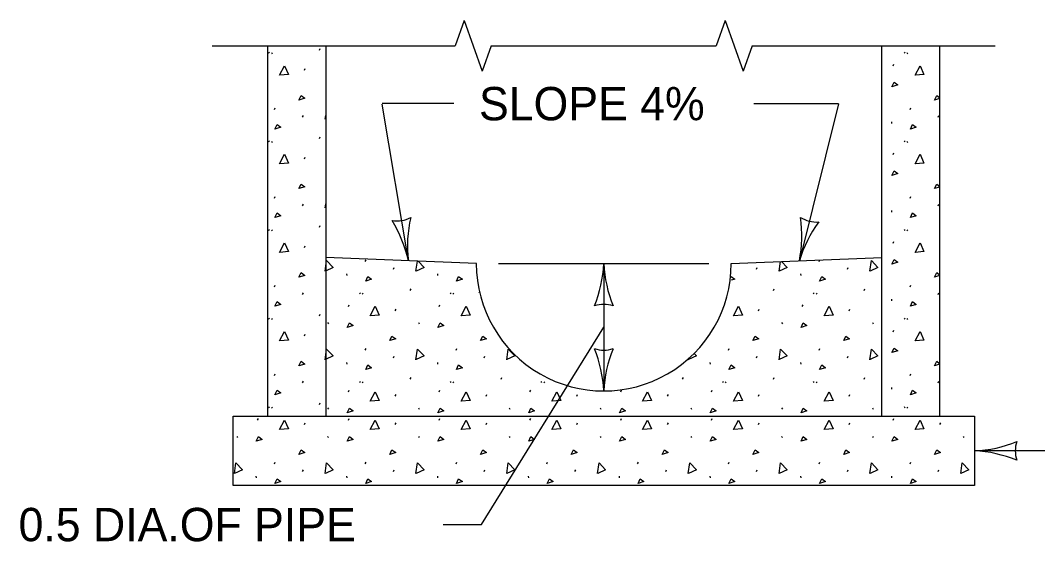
# Model space of a CAD drawing. Extents: x 49991.4 to 50028.3, y 49987.6 to 50011.4.
# Drawn here: x 50003.378 to 50005.208, y 49995.084 to 49996.022 of the extents above; entities that cross this region are included whole.
import ezdxf

# ---------------------------------------------------------------- set-up
doc = ezdxf.new("R2010")
doc.units = 0
for name, color, linetype in [('Level 1', 7, 'Continuous'), ('Level 2', 7, 'Continuous'), ('Level 3', 7, 'Continuous'), ('Level 6', 7, 'Continuous')]:
    doc.layers.add(name, color=color, linetype=linetype)

msp = doc.modelspace()

# ---------------------------------------------------------------- linework, layer by layer
at = {"layer": 'Level 1'}
for p, q in [((50003.8231, 49995.3096), (50003.8231, 49995.9763)), ((50003.9272, 49995.9763), (50003.9272, 49995.3096)), ((50004.9272, 49995.3096), (50004.9272, 49995.9763)), ((50005.0313, 49995.9763), (50005.0313, 49995.3096)), ((50003.8244, 49995.9647), (50003.8257, 49995.9627)), ((50003.8295, 49995.9639), (50003.8308, 49995.9619)), ((50003.9161, 49995.9686), (50003.9174, 49995.9716)), ((50004.9673, 49995.9647), (50004.9686, 49995.9627)), ((50004.9723, 49995.9639), (50004.9737, 49995.9619)), ((50004.9476, 49995.94), (50004.9489, 49995.943)), ((50003.8891, 49995.9323), (50003.8904, 49995.9353)), ((50003.8351, 49995.8614), (50003.8365, 49995.8644)), ((50003.8857, 49995.8478), (50003.8871, 49995.8508)), ((50004.978, 49995.8614), (50004.9793, 49995.8644)), ((50005.0286, 49995.8478), (50005.0299, 49995.8508)), ((50004.9445, 49995.8394), (50004.9449, 49995.8364)), ((50003.9161, 49995.8091), (50003.9174, 49995.8121)), ((50003.8244, 49995.8052), (50003.8257, 49995.8032)), ((50003.8295, 49995.8044), (50003.8308, 49995.8024)), ((50004.9673, 49995.8052), (50004.9686, 49995.8032)), ((50004.9723, 49995.8044), (50004.9737, 49995.8024)), ((50003.8891, 49995.7729), (50003.8904, 49995.7759)), ((50004.9476, 49995.7805), (50004.9489, 49995.7835)), ((50003.8351, 49995.702), (50003.8365, 49995.705)), ((50004.978, 49995.702), (50004.9793, 49995.705)), ((50003.8857, 49995.6883), (50003.8871, 49995.6913)), ((50005.0286, 49995.6883), (50005.0299, 49995.6913)), ((50004.9445, 49995.6799), (50004.9449, 49995.6769)), ((50003.8244, 49995.6458), (50003.8257, 49995.6438)), ((50003.9161, 49995.6497), (50003.9174, 49995.6526)), ((50004.9673, 49995.6458), (50004.9686, 49995.6438)), ((50003.8295, 49995.645), (50003.8308, 49995.643)), ((50004.9723, 49995.645), (50004.9737, 49995.643)), ((50003.8891, 49995.6134), (50003.8904, 49995.6164)), ((50004.9476, 49995.6211), (50004.9489, 49995.6241)), ((50004.1981, 49995.5842), (50003.9272, 49995.5955)), ((50003.9984, 49995.5879), (50003.9997, 49995.5909)), ((50004.6564, 49995.5842), (50004.9272, 49995.5955)), ((50004.8147, 49995.5879), (50004.8161, 49995.5908)), ((50004.049, 49995.5742), (50004.0503, 49995.5772)), ((50004.7021, 49995.5742), (50004.7034, 49995.5772)), ((50004.8653, 49995.5742), (50004.8667, 49995.5772)), ((50003.9649, 49995.5659), (50003.9653, 49995.5629)), ((50004.1282, 49995.5659), (50004.1285, 49995.5629)), ((50004.7813, 49995.5659), (50004.7816, 49995.5629)), ((50003.8351, 49995.5425), (50003.8365, 49995.5455)), ((50004.0793, 49995.5356), (50004.0807, 49995.5386)), ((50004.7324, 49995.5356), (50004.7337, 49995.5386)), ((50004.8957, 49995.5356), (50004.897, 49995.5386)), ((50004.978, 49995.5425), (50004.9793, 49995.5455)), ((50003.8857, 49995.5288), (50003.8871, 49995.5318)), ((50003.9877, 49995.5317), (50003.989, 49995.5297)), ((50003.9927, 49995.531), (50003.9941, 49995.529)), ((50004.1509, 49995.5317), (50004.1523, 49995.5297)), ((50004.156, 49995.531), (50004.1573, 49995.529)), ((50004.804, 49995.5317), (50004.8053, 49995.5297)), ((50004.8091, 49995.531), (50004.8104, 49995.529)), ((50004.9445, 49995.5205), (50004.9449, 49995.5175)), ((50005.0286, 49995.5288), (50005.0299, 49995.5318)), ((50003.968, 49995.507), (50003.9693, 49995.51)), ((50004.0523, 49995.4994), (50004.0537, 49995.5024)), ((50004.1313, 49995.507), (50004.1326, 49995.51)), ((50004.7054, 49995.4994), (50004.7067, 49995.5024)), ((50004.7843, 49995.507), (50004.7857, 49995.51)), ((50004.8687, 49995.4994), (50004.87, 49995.5024)), ((50003.8244, 49995.4863), (50003.8257, 49995.4843)), ((50003.8295, 49995.4856), (50003.8308, 49995.4836)), ((50003.9161, 49995.4902), (50003.9174, 49995.4932)), ((50004.9673, 49995.4863), (50004.9686, 49995.4843)), ((50004.9723, 49995.4856), (50004.9737, 49995.4836)), ((50003.9307, 49995.478), (50003.9321, 49995.476)), ((50004.094, 49995.478), (50004.0953, 49995.476)), ((50004.7471, 49995.478), (50004.7484, 49995.476)), ((50004.9103, 49995.478), (50004.9117, 49995.476)), ((50004.9476, 49995.4616), (50004.9489, 49995.4646)), ((50003.8891, 49995.454), (50003.8904, 49995.457)), ((50003.9984, 49995.4284), (50003.9997, 49995.4314)), ((50004.1617, 49995.4284), (50004.163, 49995.4314)), ((50004.6515, 49995.4284), (50004.6528, 49995.4314)), ((50004.8147, 49995.4284), (50004.8161, 49995.4314)), ((50004.049, 49995.4148), (50004.0503, 49995.4178)), ((50004.2123, 49995.4148), (50004.2136, 49995.4178)), ((50004.7021, 49995.4148), (50004.7034, 49995.4178)), ((50004.8653, 49995.4148), (50004.8667, 49995.4178)), ((50003.9649, 49995.4064), (50003.9653, 49995.4034)), ((50004.1282, 49995.4064), (50004.1285, 49995.4034)), ((50004.618, 49995.4064), (50004.6183, 49995.4034)), ((50004.7813, 49995.4064), (50004.7816, 49995.4034)), ((50003.8351, 49995.383), (50003.8365, 49995.386)), ((50003.8857, 49995.3694), (50003.8871, 49995.3724)), ((50003.9877, 49995.3722), (50003.989, 49995.3702)), ((50003.9927, 49995.3715), (50003.9941, 49995.3695)), ((50004.0793, 49995.3762), (50004.0807, 49995.3792)), ((50004.1509, 49995.3722), (50004.1523, 49995.3702)), ((50004.156, 49995.3715), (50004.1573, 49995.3695)), ((50004.2426, 49995.3762), (50004.2439, 49995.3792)), ((50004.3142, 49995.3722), (50004.3155, 49995.3702)), ((50004.3193, 49995.3715), (50004.3206, 49995.3695)), ((50004.5691, 49995.3762), (50004.5705, 49995.3792)), ((50004.6407, 49995.3722), (50004.6421, 49995.3702)), ((50004.6458, 49995.3715), (50004.6471, 49995.3695)), ((50004.7324, 49995.3762), (50004.7337, 49995.3792)), ((50004.804, 49995.3722), (50004.8053, 49995.3702)), ((50004.8091, 49995.3715), (50004.8104, 49995.3695)), ((50004.8957, 49995.3762), (50004.897, 49995.3792)), ((50004.978, 49995.383), (50004.9793, 49995.386)), ((50005.0286, 49995.3694), (50005.0299, 49995.3724)), ((50003.968, 49995.3534), (50003.9693, 49995.3564)), ((50004.1313, 49995.3534), (50004.1326, 49995.3564)), ((50004.2945, 49995.3534), (50004.2959, 49995.3564)), ((50004.4578, 49995.3534), (50004.4591, 49995.3564)), ((50004.6211, 49995.3534), (50004.6224, 49995.3564)), ((50004.9445, 49995.361), (50004.9449, 49995.358)), ((50004.0523, 49995.3457), (50004.0537, 49995.3487)), ((50004.2156, 49995.3457), (50004.2169, 49995.3487)), ((50004.3789, 49995.3457), (50004.3802, 49995.3487)), ((50004.5421, 49995.3457), (50004.5435, 49995.3487)), ((50004.7054, 49995.3457), (50004.7067, 49995.3487)), ((50004.8687, 49995.3457), (50004.87, 49995.3487)), ((50003.8244, 49995.3268), (50003.8257, 49995.3248)), ((50003.8295, 49995.3261), (50003.8308, 49995.3241)), ((50003.9161, 49995.3308), (50003.9174, 49995.3338)), ((50003.9307, 49995.3244), (50003.9321, 49995.3224)), ((50004.094, 49995.3244), (50004.0953, 49995.3224)), ((50004.2573, 49995.3244), (50004.2586, 49995.3224)), ((50004.4205, 49995.3244), (50004.4219, 49995.3224)), ((50004.5838, 49995.3244), (50004.5851, 49995.3224)), ((50004.7471, 49995.3244), (50004.7484, 49995.3224)), ((50004.9103, 49995.3244), (50004.9117, 49995.3224)), ((50004.9673, 49995.3268), (50004.9686, 49995.3248)), ((50004.9723, 49995.3261), (50004.9737, 49995.3241)), ((50003.7605, 49995.3096), (50005.0938, 49995.3096)), ((50003.7605, 49995.3096), (50005.0938, 49995.3096)), ((50003.7605, 49995.3096), (50005.0938, 49995.3096)), ((50003.7605, 49995.1846), (50003.7605, 49995.3096)), ((50003.8047, 49995.3022), (50003.8061, 49995.3052)), ((50003.8891, 49995.2945), (50003.8904, 49995.2975)), ((50003.968, 49995.3022), (50003.9693, 49995.3052)), ((50004.0523, 49995.2945), (50004.0537, 49995.2975)), ((50004.1313, 49995.3022), (50004.1326, 49995.3052)), ((50004.2156, 49995.2945), (50004.2169, 49995.2975)), ((50004.2945, 49995.3022), (50004.2959, 49995.3052)), ((50004.3789, 49995.2945), (50004.3802, 49995.2975)), ((50004.4578, 49995.3022), (50004.4591, 49995.3052)), ((50004.5421, 49995.2945), (50004.5435, 49995.2975)), ((50004.6211, 49995.3022), (50004.6224, 49995.3052)), ((50004.7054, 49995.2945), (50004.7067, 49995.2975)), ((50004.8687, 49995.2945), (50004.87, 49995.2975)), ((50004.9476, 49995.3022), (50004.9489, 49995.3052)), ((50005.0319, 49995.2945), (50005.0333, 49995.2975)), ((50005.0938, 49995.3096), (50005.0938, 49995.1846)), ((50003.7675, 49995.2732), (50003.7688, 49995.2712)), ((50003.9307, 49995.2732), (50003.9321, 49995.2712)), ((50004.094, 49995.2732), (50004.0953, 49995.2712)), ((50004.2573, 49995.2732), (50004.2586, 49995.2712)), ((50004.4205, 49995.2732), (50004.4219, 49995.2712)), ((50004.5838, 49995.2732), (50004.5851, 49995.2712)), ((50004.7471, 49995.2732), (50004.7484, 49995.2712)), ((50004.9103, 49995.2732), (50004.9117, 49995.2712)), ((50005.0736, 49995.2732), (50005.0749, 49995.2712)), ((50003.8351, 49995.2236), (50003.8365, 49995.2266)), ((50003.9984, 49995.2236), (50003.9997, 49995.2266)), ((50004.1617, 49995.2236), (50004.163, 49995.2266)), ((50004.3249, 49995.2236), (50004.3263, 49995.2266)), ((50004.4882, 49995.2236), (50004.4895, 49995.2266)), ((50004.6515, 49995.2236), (50004.6528, 49995.2266)), ((50004.8147, 49995.2236), (50004.8161, 49995.2266)), ((50004.978, 49995.2236), (50004.9793, 49995.2266)), ((50003.8857, 49995.2099), (50003.8871, 49995.2129)), ((50004.049, 49995.2099), (50004.0503, 49995.2129)), ((50004.2123, 49995.2099), (50004.2136, 49995.2129)), ((50004.3755, 49995.2099), (50004.3769, 49995.2129)), ((50004.5388, 49995.2099), (50004.5401, 49995.2129)), ((50004.7021, 49995.2099), (50004.7034, 49995.2129)), ((50004.8653, 49995.2099), (50004.8667, 49995.2129)), ((50005.0286, 49995.2099), (50005.0299, 49995.2129)), ((50003.8017, 49995.2016), (50003.802, 49995.1986)), ((50003.9649, 49995.2016), (50003.9653, 49995.1986)), ((50004.1282, 49995.2016), (50004.1285, 49995.1986)), ((50004.2915, 49995.2016), (50004.2918, 49995.1986)), ((50004.4547, 49995.2016), (50004.4551, 49995.1986)), ((50004.618, 49995.2016), (50004.6183, 49995.1986)), ((50004.7813, 49995.2016), (50004.7816, 49995.1986)), ((50004.9445, 49995.2016), (50004.9449, 49995.1986)), ((50005.0938, 49995.1846), (50003.7605, 49995.1846))]:
    msp.add_line(p, q, dxfattribs=at)
for points in [[(50003.8441, 49995.9234), (50003.8531, 49995.9403), (50003.8601, 49995.9247), (50003.8445, 49995.9234)], [(50004.987, 49995.9234), (50004.996, 49995.9403), (50005.003, 49995.9247), (50004.9873, 49995.9234)], [(50004.9453, 49995.9024), (50004.9493, 49995.9107), (50004.9559, 49995.9057), (50004.9453, 49995.9024)], [(50003.8791, 49995.8786), (50003.8831, 49995.8869), (50003.8898, 49995.8819), (50003.8791, 49995.8786)], [(50005.022, 49995.8786), (50005.026, 49995.8869), (50005.0313, 49995.8829)], [(50005.0313, 49995.8814), (50005.022, 49995.8786)], [(50003.9263, 49995.8443), (50003.9272, 49995.851)], [(50003.8358, 49995.8264), (50003.8398, 49995.8348), (50003.8465, 49995.8298), (50003.8358, 49995.8264)], [(50003.9272, 49995.8447), (50003.9266, 49995.8444)], [(50004.9787, 49995.8264), (50004.9827, 49995.8348), (50004.9893, 49995.8298), (50004.9787, 49995.8264)], [(50003.8441, 49995.7639), (50003.8531, 49995.7809), (50003.8601, 49995.7652), (50003.8445, 49995.7639)], [(50004.987, 49995.7639), (50004.996, 49995.7809), (50005.003, 49995.7652), (50004.9873, 49995.7639)], [(50004.9453, 49995.7429), (50004.9493, 49995.7512), (50004.9559, 49995.7462), (50004.9453, 49995.7429)], [(50003.8791, 49995.7191), (50003.8831, 49995.7274), (50003.8898, 49995.7224), (50003.8791, 49995.7191)], [(50005.022, 49995.7191), (50005.026, 49995.7274), (50005.0313, 49995.7234)], [(50005.0313, 49995.722), (50005.022, 49995.7191)], [(50003.9263, 49995.6848), (50003.9272, 49995.6916)], [(50003.9272, 49995.6852), (50003.9266, 49995.685)], [(50003.8358, 49995.667), (50003.8398, 49995.6753), (50003.8465, 49995.6703), (50003.8358, 49995.667)], [(50004.9787, 49995.667), (50004.9827, 49995.6753), (50004.9893, 49995.6703), (50004.9787, 49995.667)], [(50003.8441, 49995.6044), (50003.8531, 49995.6214), (50003.8601, 49995.6058), (50003.8445, 49995.6044)], [(50004.987, 49995.6044), (50004.996, 49995.6214), (50005.003, 49995.6058), (50004.9873, 49995.6044)], [(50004.9453, 49995.5834), (50004.9493, 49995.5918), (50004.9559, 49995.5868), (50004.9453, 49995.5834)], [(50003.9263, 49995.5708), (50003.9289, 49995.5898), (50003.9408, 49995.5775), (50003.9266, 49995.5709)], [(50004.0895, 49995.5708), (50004.092, 49995.5886)], [(50004.0934, 49995.5886), (50004.1041, 49995.5775), (50004.0899, 49995.5709)], [(50004.7426, 49995.5708), (50004.7449, 49995.5879)], [(50004.747, 49995.588), (50004.7571, 49995.5775), (50004.7429, 49995.5709)], [(50004.9059, 49995.5708), (50004.9085, 49995.5898), (50004.9204, 49995.5775), (50004.9062, 49995.5709)], [(50003.8791, 49995.5596), (50003.8831, 49995.568), (50003.8898, 49995.563), (50003.8791, 49995.5596)], [(50003.9991, 49995.5529), (50004.0031, 49995.5612), (50004.0097, 49995.5562), (50003.9991, 49995.5529)], [(50004.1623, 49995.5529), (50004.1663, 49995.5612), (50004.173, 49995.5562), (50004.1623, 49995.5529)], [(50004.6562, 49995.5612), (50004.6628, 49995.5562), (50004.6562, 49995.5542)], [(50004.8154, 49995.5529), (50004.8194, 49995.5612), (50004.8261, 49995.5562), (50004.8154, 49995.5529)], [(50005.022, 49995.5596), (50005.026, 49995.568), (50005.0313, 49995.564)], [(50005.0313, 49995.5626), (50005.022, 49995.5596)], [(50004.2032, 49995.5324), (50004.2033, 49995.5327)], [(50004.2034, 49995.5324), (50004.2032, 49995.5324)], [(50003.8358, 49995.5075), (50003.8398, 49995.5158), (50003.8465, 49995.5108), (50003.8358, 49995.5075)], [(50004.0074, 49995.4904), (50004.0164, 49995.5074), (50004.0234, 49995.4917), (50004.0077, 49995.4904)], [(50004.1707, 49995.4904), (50004.1797, 49995.5074), (50004.1867, 49995.4917), (50004.171, 49995.4904)], [(50004.6605, 49995.4904), (50004.6695, 49995.5074), (50004.6765, 49995.4917), (50004.6608, 49995.4904)], [(50004.8237, 49995.4904), (50004.8327, 49995.5074), (50004.8397, 49995.4917), (50004.8241, 49995.4904)], [(50004.9787, 49995.5075), (50004.9827, 49995.5158), (50004.9893, 49995.5108), (50004.9787, 49995.5075)], [(50003.9657, 49995.4694), (50003.9697, 49995.4777), (50003.9763, 49995.4727), (50003.9657, 49995.4694)], [(50004.1289, 49995.4694), (50004.1329, 49995.4777), (50004.1396, 49995.4727), (50004.1289, 49995.4694)], [(50004.782, 49995.4694), (50004.786, 49995.4777), (50004.7927, 49995.4727), (50004.782, 49995.4694)], [(50003.8441, 49995.445), (50003.8531, 49995.462), (50003.8601, 49995.4463), (50003.8445, 49995.445)], [(50004.0424, 49995.4456), (50004.0464, 49995.4539), (50004.0531, 49995.4489), (50004.0424, 49995.4456)], [(50004.2057, 49995.4456), (50004.2097, 49995.4539), (50004.2163, 49995.4489), (50004.2057, 49995.4456)], [(50004.6955, 49995.4456), (50004.6995, 49995.4539), (50004.7061, 49995.4489), (50004.6955, 49995.4456)], [(50004.8587, 49995.4456), (50004.8627, 49995.4539), (50004.8694, 49995.4489), (50004.8587, 49995.4456)], [(50004.987, 49995.445), (50004.996, 49995.462), (50005.003, 49995.4463), (50004.9873, 49995.445)], [(50003.9263, 49995.4113), (50003.9289, 49995.4304), (50003.9408, 49995.418), (50003.9266, 49995.4114)], [(50004.0895, 49995.4113), (50004.0922, 49995.4304), (50004.1041, 49995.418), (50004.0899, 49995.4114)], [(50004.2528, 49995.4113), (50004.2555, 49995.4304), (50004.2674, 49995.418), (50004.2531, 49995.4114)], [(50004.7426, 49995.4113), (50004.7452, 49995.4304), (50004.7571, 49995.418), (50004.7429, 49995.4114)], [(50004.9059, 49995.4113), (50004.9085, 49995.4304), (50004.9204, 49995.418), (50004.9062, 49995.4114)], [(50004.9453, 49995.424), (50004.9493, 49995.4323), (50004.9559, 49995.4273), (50004.9453, 49995.424)], [(50003.8791, 49995.4002), (50003.8831, 49995.4085), (50003.8898, 49995.4035), (50003.8791, 49995.4002)], [(50004.5793, 49995.4113), (50004.5795, 49995.4122)], [(50004.5896, 49995.4225), (50004.5939, 49995.418), (50004.5797, 49995.4114)], [(50005.022, 49995.4002), (50005.026, 49995.4085), (50005.0313, 49995.4046)], [(50003.9991, 49995.3935), (50004.0031, 49995.4018), (50004.0097, 49995.3968), (50003.9991, 49995.3935)], [(50004.1623, 49995.3935), (50004.1663, 49995.4018), (50004.173, 49995.3968), (50004.1623, 49995.3935)], [(50004.6521, 49995.3935), (50004.6561, 49995.4018), (50004.6628, 49995.3968), (50004.6521, 49995.3935)], [(50004.8154, 49995.3935), (50004.8194, 49995.4018), (50004.8261, 49995.3968), (50004.8154, 49995.3935)], [(50005.0313, 49995.4031), (50005.022, 49995.4002)], [(50003.8358, 49995.3481), (50003.8398, 49995.3564), (50003.8465, 49995.3514), (50003.8358, 49995.3481)], [(50004.0074, 49995.3367), (50004.0164, 49995.3537), (50004.0234, 49995.338), (50004.0077, 49995.3367)], [(50004.1707, 49995.3367), (50004.1797, 49995.3537), (50004.1867, 49995.338), (50004.171, 49995.3367)], [(50004.3339, 49995.3367), (50004.3429, 49995.3537), (50004.3499, 49995.338), (50004.3343, 49995.3367)], [(50004.4972, 49995.3367), (50004.5062, 49995.3537), (50004.5132, 49995.338), (50004.4975, 49995.3367)], [(50004.6605, 49995.3367), (50004.6695, 49995.3537), (50004.6765, 49995.338), (50004.6608, 49995.3367)], [(50004.8237, 49995.3367), (50004.8327, 49995.3537), (50004.8397, 49995.338), (50004.8241, 49995.3367)], [(50004.9787, 49995.3481), (50004.9827, 49995.3564), (50004.9893, 49995.3514), (50004.9787, 49995.3481)], [(50003.9657, 49995.3158), (50003.9697, 49995.3241), (50003.9763, 49995.3191), (50003.9657, 49995.3158)], [(50004.1289, 49995.3158), (50004.1329, 49995.3241), (50004.1396, 49995.3191), (50004.1289, 49995.3158)], [(50004.2922, 49995.3158), (50004.2962, 49995.3241), (50004.3029, 49995.3191), (50004.2922, 49995.3158)], [(50004.4555, 49995.3158), (50004.4595, 49995.3241), (50004.4661, 49995.3191), (50004.4555, 49995.3158)], [(50004.6187, 49995.3158), (50004.6227, 49995.3241), (50004.6294, 49995.3191), (50004.6187, 49995.3158)], [(50004.782, 49995.3158), (50004.786, 49995.3241), (50004.7927, 49995.3191), (50004.782, 49995.3158)], [(50003.8441, 49995.2855), (50003.8531, 49995.3025), (50003.8601, 49995.2868), (50003.8445, 49995.2855)], [(50004.0074, 49995.2855), (50004.0164, 49995.3025), (50004.0234, 49995.2868), (50004.0077, 49995.2855)], [(50004.1707, 49995.2855), (50004.1797, 49995.3025), (50004.1867, 49995.2868), (50004.171, 49995.2855)], [(50004.3339, 49995.2855), (50004.3429, 49995.3025), (50004.3499, 49995.2868), (50004.3343, 49995.2855)], [(50004.4972, 49995.2855), (50004.5062, 49995.3025), (50004.5132, 49995.2868), (50004.4975, 49995.2855)], [(50004.6605, 49995.2855), (50004.6695, 49995.3025), (50004.6765, 49995.2868), (50004.6608, 49995.2855)], [(50004.8237, 49995.2855), (50004.8327, 49995.3025), (50004.8397, 49995.2868), (50004.8241, 49995.2855)], [(50004.987, 49995.2855), (50004.996, 49995.3025), (50005.003, 49995.2868), (50004.9873, 49995.2855)], [(50003.8024, 49995.2646), (50003.8064, 49995.2729), (50003.8131, 49995.2679), (50003.8024, 49995.2646)], [(50003.9657, 49995.2646), (50003.9697, 49995.2729), (50003.9763, 49995.2679), (50003.9657, 49995.2646)], [(50004.1289, 49995.2646), (50004.1329, 49995.2729), (50004.1396, 49995.2679), (50004.1289, 49995.2646)], [(50004.2922, 49995.2646), (50004.2962, 49995.2729), (50004.3029, 49995.2679), (50004.2922, 49995.2646)], [(50004.4555, 49995.2646), (50004.4595, 49995.2729), (50004.4661, 49995.2679), (50004.4555, 49995.2646)], [(50004.6187, 49995.2646), (50004.6227, 49995.2729), (50004.6294, 49995.2679), (50004.6187, 49995.2646)], [(50004.782, 49995.2646), (50004.786, 49995.2729), (50004.7927, 49995.2679), (50004.782, 49995.2646)], [(50004.9453, 49995.2646), (50004.9493, 49995.2729), (50004.9559, 49995.2679), (50004.9453, 49995.2646)], [(50003.8791, 49995.2407), (50003.8831, 49995.249), (50003.8898, 49995.2441), (50003.8791, 49995.2407)], [(50004.0424, 49995.2407), (50004.0464, 49995.249), (50004.0531, 49995.2441), (50004.0424, 49995.2407)], [(50004.2057, 49995.2407), (50004.2097, 49995.249), (50004.2163, 49995.2441), (50004.2057, 49995.2407)], [(50004.3689, 49995.2407), (50004.3729, 49995.249), (50004.3796, 49995.2441), (50004.3689, 49995.2407)], [(50004.5322, 49995.2407), (50004.5362, 49995.249), (50004.5429, 49995.2441), (50004.5322, 49995.2407)], [(50004.6955, 49995.2407), (50004.6995, 49995.249), (50004.7061, 49995.2441), (50004.6955, 49995.2407)], [(50004.8587, 49995.2407), (50004.8627, 49995.249), (50004.8694, 49995.2441), (50004.8587, 49995.2407)], [(50005.022, 49995.2407), (50005.026, 49995.249), (50005.0327, 49995.2441), (50005.022, 49995.2407)], [(50003.763, 49995.2065), (50003.7657, 49995.2255), (50003.7776, 49995.2132), (50003.7633, 49995.2066)], [(50003.9263, 49995.2065), (50003.9289, 49995.2255), (50003.9408, 49995.2132), (50003.9266, 49995.2066)], [(50004.0895, 49995.2065), (50004.0922, 49995.2255), (50004.1041, 49995.2132), (50004.0899, 49995.2066)], [(50004.2528, 49995.2065), (50004.2555, 49995.2255), (50004.2674, 49995.2132), (50004.2531, 49995.2066)], [(50004.4161, 49995.2065), (50004.4187, 49995.2255), (50004.4306, 49995.2132), (50004.4164, 49995.2066)], [(50004.5793, 49995.2065), (50004.582, 49995.2255), (50004.5939, 49995.2132), (50004.5797, 49995.2066)], [(50004.7426, 49995.2065), (50004.7452, 49995.2255), (50004.7571, 49995.2132), (50004.7429, 49995.2066)], [(50004.9059, 49995.2065), (50004.9085, 49995.2255), (50004.9204, 49995.2132), (50004.9062, 49995.2066)], [(50005.0691, 49995.2065), (50005.0718, 49995.2255), (50005.0837, 49995.2132), (50005.0695, 49995.2066)], [(50003.8358, 49995.1886), (50003.8398, 49995.197), (50003.8465, 49995.192), (50003.8358, 49995.1886)], [(50003.9991, 49995.1886), (50004.0031, 49995.197), (50004.0097, 49995.192), (50003.9991, 49995.1886)], [(50004.1623, 49995.1886), (50004.1663, 49995.197), (50004.173, 49995.192), (50004.1623, 49995.1886)], [(50004.3256, 49995.1886), (50004.3296, 49995.197), (50004.3363, 49995.192), (50004.3256, 49995.1886)], [(50004.4889, 49995.1886), (50004.4929, 49995.197), (50004.4995, 49995.192), (50004.4889, 49995.1886)], [(50004.6521, 49995.1886), (50004.6561, 49995.197), (50004.6628, 49995.192), (50004.6521, 49995.1886)], [(50004.8154, 49995.1886), (50004.8194, 49995.197), (50004.8261, 49995.192), (50004.8154, 49995.1886)], [(50004.9787, 49995.1886), (50004.9827, 49995.197), (50004.9893, 49995.192), (50004.9787, 49995.1886)], [(50005.0847, 49995.1848), (50005.0846, 49995.1846)]]:
    msp.add_lwpolyline(points, dxfattribs=at)
msp.add_arc((50004.4272, 49995.5842), 0.2292, 180, 0.0005, dxfattribs=at)
at = {"layer": 'Level 3'}
for p, q in [((50004.1576, 49995.8721), (50004.029, 49995.8721)), ((50004.0758, 49995.5893), (50004.029, 49995.8712)), ((50004.697, 49995.8721), (50004.8492, 49995.8721)), ((50004.8492, 49995.872), (50004.7791, 49995.5893)), ((50004.2381, 49995.5842), (50004.6164, 49995.5842)), ((50004.4272, 49995.5842), (50004.4272, 49995.355)), ((50005.2672, 49995.2471), (50005.0938, 49995.2471))]:
    msp.add_line(p, q, dxfattribs=at)
msp.add_lwpolyline([(50004.1384, 49995.1146), (50004.2072, 49995.1146), (50004.4272, 49995.4696)], dxfattribs=at)
for centre, radius, start, end in [((50004.0549, 49995.7158), 0.0548, 261.5504, 297.2728), ((50004.2965, 49995.6166), 0.2223, 166.8676, 187.0511), ((50004.5504, 49995.6341), 0.233, 348.9053, 8.1552), ((50004.8099, 49995.7138), 0.0548, 238.2168, 273.9392), ((50003.8481, 49995.5399), 0.233, 12.2389, 31.4887), ((50004.9925, 49995.527), 0.2223, 143.534, 163.7175), ((50004.2051, 49995.5934), 0.2223, 337.456, 357.6395), ((50004.66, 49995.5957), 0.233, 182.8273, 202.0772), ((50004.4272, 49995.456), 0.0548, 72.1388, 107.8612), ((50004.4272, 49995.4833), 0.0548, 252.1388, 287.8612), ((50004.1945, 49995.3435), 0.233, 2.8273, 22.0772), ((50004.6494, 49995.3459), 0.2223, 157.456, 177.6395), ((50005.0824, 49995.4798), 0.233, 272.8273, 292.0772), ((50005.0824, 49995.4798), 0.233, 272.8273, 292.0772), ((50005.2221, 49995.2471), 0.0548, 162.1388, 197.8612), ((50005.2221, 49995.2471), 0.0548, 162.1388, 197.8612), ((50005.0847, 49995.025), 0.2223, 67.456, 87.6395), ((50005.0847, 49995.025), 0.2223, 67.456, 87.6395)]:
    msp.add_arc(centre, radius, start, end, dxfattribs=at)
at = {"layer": 'Level 6'}
for p, q in [((50004.1763, 49996.022), (50004.1601, 49995.9763)), ((50004.1763, 49996.022), (50004.1925, 49995.9763)), ((50004.6457, 49996.022), (50004.6295, 49995.9763)), ((50004.6457, 49996.022), (50004.6619, 49995.9763)), ((50003.7231, 49995.9763), (50004.1601, 49995.9763)), ((50004.1925, 49995.9763), (50004.2087, 49995.9306)), ((50004.2249, 49995.9763), (50004.2087, 49995.9306)), ((50004.2249, 49995.9763), (50004.6295, 49995.9763)), ((50004.6619, 49995.9763), (50004.6781, 49995.9306)), ((50004.6943, 49995.9763), (50004.6781, 49995.9306)), ((50004.6943, 49995.9763), (50005.1313, 49995.9763))]:
    msp.add_line(p, q, dxfattribs=at)

# ---------------------------------------------------------------- texts
at = {"layer": 'Level 2'}
for s, p in [('SLOPE 4%', (50004.2029, 49995.8421)), ('0.5 DIA.OF PIPE', (50003.3749, 49995.0846))]:
    msp.add_text(s, height=0.06, dxfattribs=at).set_placement(p)

doc.saveas('drawing.dxf')
